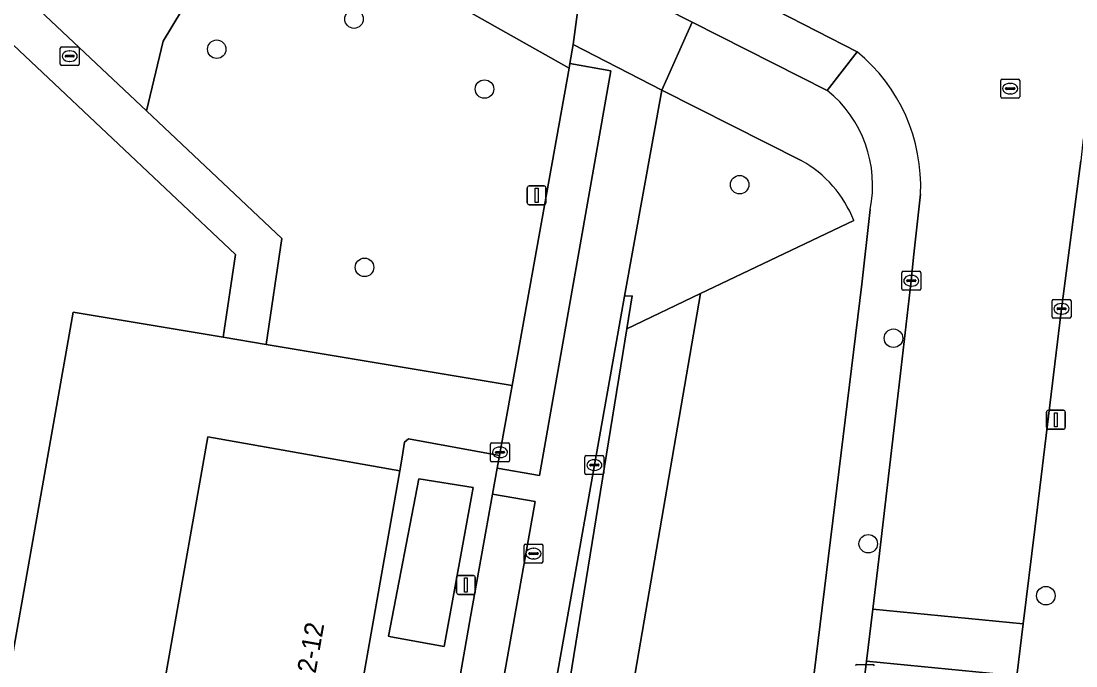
# Model space of a CAD drawing. Extents: x 161402 to 161933, y 381647 to 382315.
# Drawn here: x 161750.9 to 161806.7, y 381914.9 to 381949 of the extents above; entities that cross this region are included whole.
import ezdxf

# ---------------------------------------------------------------- set-up
doc = ezdxf.new("R2010")
doc.units = 0
for name, color, linetype in [('IMGEO_Boom', 7, 'Continuous'), ('IMGEO_Groenvoorziening', 7, 'Continuous'), ('IMGEO_Haag', 7, 'Continuous'), ('IMGEO_Kolk', 7, 'Continuous'), ('IMGEO_Lichtmast', 7, 'Continuous'), ('IMGEO_Pand', 7, 'Continuous'), ('IMGEO_Pand_nummerreeks', 7, 'Continuous'), ('IMGEO_Parkeervlak_open', 7, 'Continuous'), ('IMGEO_Rijbaan_lokaal_open', 7, 'Continuous'), ('IMGEO_Rioolput', 7, 'Continuous'), ('IMGEO_Voetpad_open', 7, 'Continuous')]:
    doc.layers.add(name, color=color, linetype=linetype)

msp = doc.modelspace()

# ---------------------------------------------------------------- linework, layer by layer
at = {"layer": 'IMGEO_Boom'}
for centre in [(161768.484, 381949.129), (161761.223, 381947.536), (161775.384, 381945.427), (161788.881, 381940.368), (161769.038, 381935.994), (161797.017, 381932.244), (161795.68, 381921.369), (161805.076, 381918.621)]:
    msp.add_circle(centre, 0.489, dxfattribs=at)
at = {"layer": 'IMGEO_Groenvoorziening'}
for points in [[(161757.71, 381973.064), (161752.256, 381970.922), (161752.331, 381970.789), (161752.352, 381970.751), (161756.323, 381963.676), (161759.452, 381960.205), (161755.303, 381956.704), (161754.882, 381956.037), (161751.868, 381949.589), (161757.507, 381944.274), (161758.386, 381947.963), (161763.392, 381956.267), (161767.079, 381953.278), (161771.629, 381951.189), (161779.856, 381946.528), (161779.9, 381946.775), (161780.082, 381947.784), (161780.63, 381951.898), (161779.002, 381952.721), (161777.972, 381953.284)], [(161737.696, 381886.61), (161738.528, 381891.149), (161746.013, 381890.587), (161753.635, 381933.615), (161761.561, 381932.294), (161762.216, 381936.676), (161748.594, 381949.514), (161744.47, 381949.999)], [(161793.514, 381945.349), (161786.367, 381948.968), (161784.762, 381945.37), (161792.141, 381941.646)], [(161792.141, 381941.646), (161784.762, 381945.37), (161782.784, 381934.462), (161783.2, 381934.478), (161782.918, 381932.741), (161786.816, 381934.618), (161794.921, 381938.465)], [(161795.348, 381935.098), (161795.777, 381939.049)], [(161794.921, 381938.465), (161786.816, 381934.618), (161779.814, 381893.915), (161788.716, 381884.216), (161790.718, 381897.39), (161795.348, 381935.098)], [(161768.961, 381885.978), (161758.322, 381887.744), (161758.545, 381889.099), (161758.611, 381889.504), (161754.257, 381890.274), (161757.508, 381908.649), (161760.759, 381927.025), (161770.911, 381925.228), (161771.029, 381925.951), (161771.159, 381926.744), (161771.362, 381926.92), (161776.174, 381926.042), (161776.84, 381929.749), (161763.83, 381931.916), (161761.561, 381932.294), (161753.635, 381933.615), (161746.013, 381890.587), (161744.878, 381884.178)]]:
    msp.add_lwpolyline(points, dxfattribs=at)
for points in [[(161757.507, 381944.274), (161764.668, 381937.525), (161763.83, 381931.916), (161776.84, 381929.749), (161779.856, 381946.528), (161771.629, 381951.189), (161767.079, 381953.278), (161763.392, 381956.267), (161758.386, 381947.963)], [(161764.668, 381937.525), (161757.507, 381944.274), (161751.868, 381949.589), (161749.618, 381951.709), (161744.458, 381952.316), (161744.47, 381949.999), (161748.594, 381949.514), (161762.216, 381936.676), (161761.561, 381932.294), (161763.83, 381931.916)], [(161782.918, 381932.741), (161783.2, 381934.478), (161782.784, 381934.462), (161775.497, 381893.39), (161776.5, 381893.226), (161776.924, 381895.837), (161777.092, 381896.872)], [(161779.814, 381893.915), (161786.816, 381934.618), (161782.918, 381932.741), (161777.092, 381896.872)], [(161774.788, 381924.343), (161771.914, 381924.8), (161770.307, 381916.473), (161770.437, 381916.449), (161773.256, 381915.934)]]:
    msp.add_lwpolyline(points, close=True, dxfattribs=at)
for centre, radius, start, end in [((161789.511, 381940.355), 6.401, 348.231, 51.2862), ((161789.052, 381936.141), 6.312, 21.6009, 60.702), ((161789.052, 381936.141), 6.312, 21.6009, 60.702)]:
    msp.add_arc(centre, radius, start, end, dxfattribs=at)
at = {"layer": 'IMGEO_Haag'}
msp.add_lwpolyline([(161782.918, 381932.741), (161783.2, 381934.478), (161782.784, 381934.462), (161775.497, 381893.39), (161776.5, 381893.226), (161776.924, 381895.837), (161777.092, 381896.872)], close=True, dxfattribs=at)
at = {"layer": 'IMGEO_Kolk'}
for p, q in [((161797.459, 381934.859), (161797.459, 381935.711)), ((161797.534, 381935.785), (161798.386, 381935.785)), ((161797.947, 381935.565), (161797.972, 381935.565)), ((161798.46, 381935.711), (161798.46, 381934.859)), ((161797.718, 381935.279), (161797.718, 381935.291)), ((161798.156, 381935.242), (161797.758, 381935.242)), ((161797.761, 381935.328), (161798.159, 381935.328)), ((161797.97, 381935.005), (161797.945, 381935.005)), ((161798.202, 381935.291), (161798.202, 381935.279)), ((161798.386, 381934.785), (161797.534, 381934.785)), ((161805.482, 381934.3), (161806.334, 381934.3)), ((161805.407, 381933.374), (161805.407, 381934.226)), ((161805.666, 381933.794), (161805.666, 381933.806)), ((161806.104, 381933.757), (161805.706, 381933.757)), ((161805.709, 381933.843), (161806.107, 381933.843)), ((161805.895, 381934.08), (161805.92, 381934.08)), ((161806.15, 381933.806), (161806.15, 381933.794)), ((161806.408, 381934.226), (161806.408, 381933.374)), ((161806.334, 381933.3), (161805.482, 381933.3)), ((161805.918, 381933.52), (161805.893, 381933.52)), ((161775.704, 381925.78), (161775.704, 381926.632)), ((161775.779, 381926.706), (161776.631, 381926.706)), ((161776.192, 381926.486), (161776.217, 381926.486)), ((161776.705, 381926.632), (161776.705, 381925.78)), ((161775.963, 381926.2), (161775.963, 381926.212)), ((161776.401, 381926.163), (161776.003, 381926.163)), ((161776.006, 381926.249), (161776.404, 381926.249)), ((161776.215, 381925.926), (161776.19, 381925.926)), ((161776.447, 381926.212), (161776.447, 381926.2)), ((161780.695, 381925.106), (161780.695, 381925.958)), ((161780.77, 381926.032), (161781.622, 381926.032)), ((161781.696, 381925.958), (161781.696, 381925.106)), ((161776.631, 381925.706), (161775.779, 381925.706)), ((161780.954, 381925.526), (161780.954, 381925.538)), ((161781.392, 381925.489), (161780.994, 381925.489)), ((161780.997, 381925.575), (161781.395, 381925.575)), ((161781.183, 381925.812), (161781.208, 381925.812)), ((161781.438, 381925.538), (161781.438, 381925.526)), ((161781.622, 381925.032), (161780.77, 381925.032)), ((161781.206, 381925.252), (161781.181, 381925.252)), ((161795.079, 381914.979), (161795.931, 381914.979))]:
    msp.add_line(p, q, dxfattribs=at)
for points in [[(161797.459, 381934.859), (161797.459, 381935.711)], [(161797.534, 381935.785), (161798.386, 381935.785)], [(161798.46, 381935.711), (161798.46, 381934.859)], [(161798.386, 381934.785), (161797.534, 381934.785)], [(161805.482, 381934.3), (161806.334, 381934.3)], [(161805.407, 381933.374), (161805.407, 381934.226)], [(161806.408, 381934.226), (161806.408, 381933.374)], [(161806.334, 381933.3), (161805.482, 381933.3)], [(161775.704, 381925.78), (161775.704, 381926.632)], [(161775.779, 381926.706), (161776.631, 381926.706)], [(161776.705, 381926.632), (161776.705, 381925.78)], [(161780.695, 381925.106), (161780.695, 381925.958)], [(161780.77, 381926.032), (161781.622, 381926.032)], [(161781.696, 381925.958), (161781.696, 381925.106)], [(161776.631, 381925.706), (161775.779, 381925.706)], [(161781.622, 381925.032), (161780.77, 381925.032)], [(161795.079, 381914.979), (161795.931, 381914.979)]]:
    msp.add_lwpolyline(points, dxfattribs=at)
for centre, radius, start, end in [((161797.536, 381935.709), 0.0765, 91.552, 178.448), ((161797.536, 381935.709), 0.0765, 91.552, 178.448), ((161798.384, 381935.709), 0.0765, 1.552, 88.448), ((161798.384, 381935.709), 0.0765, 1.552, 88.448), ((161797.536, 381934.861), 0.0765, 181.552, 268.448), ((161797.536, 381934.861), 0.0765, 181.552, 268.448), ((161797.758, 381935.288), 0.0403, 85.8775, 175.7526), ((161797.755, 381935.278), 0.0366, 178.938, 274.7102), ((161798.159, 381935.285), 0.043, 264.8664, 352.4533), ((161798.163, 381935.29), 0.0386, 1.7309, 96.639), ((161798.384, 381934.861), 0.0765, 271.552, 358.448), ((161798.384, 381934.861), 0.0765, 271.552, 358.448), ((161805.484, 381934.224), 0.0765, 91.552, 178.448), ((161805.484, 381934.224), 0.0765, 91.552, 178.448), ((161806.332, 381934.224), 0.0765, 1.552, 88.448), ((161806.332, 381934.224), 0.0765, 1.552, 88.448), ((161805.706, 381933.803), 0.0403, 85.8775, 175.7526), ((161805.703, 381933.793), 0.0366, 178.938, 274.7102), ((161806.107, 381933.8), 0.043, 264.8664, 352.4533), ((161806.111, 381933.805), 0.0386, 1.7309, 96.639), ((161805.484, 381933.376), 0.0765, 181.552, 268.448), ((161805.484, 381933.376), 0.0765, 181.552, 268.448), ((161806.332, 381933.376), 0.0765, 271.552, 358.448), ((161806.332, 381933.376), 0.0765, 271.552, 358.448), ((161775.781, 381926.63), 0.0765, 91.552, 178.448), ((161775.781, 381926.63), 0.0765, 91.552, 178.448), ((161776.629, 381926.63), 0.0765, 1.552, 88.448), ((161776.629, 381926.63), 0.0765, 1.552, 88.448), ((161776.003, 381926.209), 0.0403, 85.8775, 175.7526), ((161776, 381926.199), 0.0366, 178.938, 274.7102), ((161776.404, 381926.206), 0.043, 264.8664, 352.4533), ((161776.408, 381926.211), 0.0386, 1.7309, 96.639), ((161780.772, 381925.956), 0.0765, 91.552, 178.448), ((161780.772, 381925.956), 0.0765, 91.552, 178.448), ((161781.62, 381925.956), 0.0765, 1.552, 88.448), ((161781.62, 381925.956), 0.0765, 1.552, 88.448), ((161775.781, 381925.782), 0.0765, 181.552, 268.448), ((161775.781, 381925.782), 0.0765, 181.552, 268.448), ((161776.629, 381925.782), 0.0765, 271.552, 358.448), ((161776.629, 381925.782), 0.0765, 271.552, 358.448), ((161780.994, 381925.535), 0.0403, 85.8775, 175.7526), ((161780.991, 381925.525), 0.0366, 178.938, 274.7102), ((161781.395, 381925.532), 0.043, 264.8664, 352.4533), ((161781.399, 381925.537), 0.0386, 1.7309, 96.639), ((161780.772, 381925.108), 0.0765, 181.552, 268.448), ((161780.772, 381925.108), 0.0765, 181.552, 268.448), ((161781.62, 381925.108), 0.0765, 271.552, 358.448), ((161781.62, 381925.108), 0.0765, 271.552, 358.448), ((161795.081, 381914.903), 0.0765, 91.552, 178.448), ((161795.081, 381914.903), 0.0765, 91.552, 178.448), ((161795.929, 381914.903), 0.0765, 1.552, 88.448), ((161795.929, 381914.903), 0.0765, 1.552, 88.448)]:
    msp.add_arc(centre, radius, start, end, dxfattribs=at)
for centre, major_axis, ratio, start_param, end_param in [((161797.946, 381935.285), (-0.387, 0.002), 0.722429, 4.712389, 7.853982), ((161797.971, 381935.285), (-0.39, 0.002), 0.717154, 1.570796, 4.712389), ((161805.894, 381933.8), (-0.387, 0.002), 0.722429, 4.712389, 7.853982), ((161805.919, 381933.8), (-0.39, 0.002), 0.717154, 1.570796, 4.712389), ((161776.191, 381926.206), (-0.387, 0.002), 0.722429, 4.712389, 7.853982), ((161776.216, 381926.206), (-0.39, 0.002), 0.717154, 1.570796, 4.712389), ((161781.182, 381925.532), (-0.387, 0.002), 0.722429, 4.712389, 7.853982), ((161781.207, 381925.532), (-0.39, 0.002), 0.717154, 1.570796, 4.712389)]:
    msp.add_ellipse(centre, major_axis=major_axis, ratio=ratio, start_param=start_param, end_param=end_param, dxfattribs=at)
at = {"layer": 'IMGEO_Lichtmast'}
for p, q in [((161777.645, 381939.403), (161777.645, 381940.203)), ((161777.645, 381940.203), (161777.645, 381939.403)), ((161777.745, 381940.303), (161778.535, 381940.303)), ((161778.535, 381940.303), (161777.745, 381940.303)), ((161778.635, 381940.203), (161778.635, 381939.403)), ((161778.635, 381939.403), (161778.635, 381940.203)), ((161778.535, 381939.303), (161777.745, 381939.303)), ((161777.745, 381939.303), (161778.535, 381939.303)), ((161805.111, 381927.529), (161805.111, 381928.329)), ((161805.111, 381928.329), (161805.111, 381927.529)), ((161805.211, 381928.429), (161806.001, 381928.429)), ((161806.001, 381928.429), (161805.211, 381928.429)), ((161806.101, 381928.329), (161806.101, 381927.529)), ((161806.101, 381927.529), (161806.101, 381928.329)), ((161806.001, 381927.429), (161805.211, 381927.429)), ((161805.211, 381927.429), (161806.001, 381927.429)), ((161773.905, 381918.786), (161773.905, 381919.586)), ((161773.905, 381919.586), (161773.905, 381918.786)), ((161774.005, 381919.686), (161774.795, 381919.686)), ((161774.795, 381919.686), (161774.005, 381919.686)), ((161774.895, 381919.586), (161774.895, 381918.786)), ((161774.895, 381918.786), (161774.895, 381919.586)), ((161774.795, 381918.686), (161774.005, 381918.686)), ((161774.005, 381918.686), (161774.795, 381918.686))]:
    msp.add_line(p, q, dxfattribs=at)
for points in [[(161778.065, 381940.178), (161778.215, 381940.178), (161778.215, 381939.428), (161778.065, 381939.428), (161778.065, 381940.178)], [(161805.531, 381928.304), (161805.681, 381928.304), (161805.681, 381927.554), (161805.531, 381927.554), (161805.531, 381928.304)], [(161774.325, 381919.561), (161774.475, 381919.561), (161774.475, 381918.811), (161774.325, 381918.811), (161774.325, 381919.561)]]:
    msp.add_lwpolyline(points, dxfattribs=at)
for centre, start, end in [((161777.745, 381940.203), 90, 180), ((161777.745, 381940.203), 90, 180), ((161778.535, 381940.203), 0, 90), ((161778.535, 381940.203), 360, 90), ((161777.745, 381939.403), 180, 270), ((161777.745, 381939.403), 180, 270), ((161778.535, 381939.403), 270, 0), ((161778.535, 381939.403), 270, 0), ((161805.211, 381928.329), 90, 180), ((161805.211, 381928.329), 90, 180), ((161806.001, 381928.329), 0, 90), ((161806.001, 381928.329), 360, 90), ((161805.211, 381927.529), 180, 270), ((161805.211, 381927.529), 180, 270), ((161806.001, 381927.529), 270, 0), ((161806.001, 381927.529), 270, 0), ((161774.005, 381919.586), 90, 180), ((161774.005, 381919.586), 90, 180), ((161774.795, 381919.586), 0, 90), ((161774.795, 381919.586), 360, 90), ((161774.005, 381918.786), 180, 270), ((161774.005, 381918.786), 180, 270), ((161774.795, 381918.786), 270, 0), ((161774.795, 381918.786), 270, 0)]:
    msp.add_arc(centre, 0.1, start, end, dxfattribs=at)
at = {"layer": 'IMGEO_Pand'}
msp.add_lwpolyline([(161757.508, 381908.649), (161767.659, 381906.853), (161770.911, 381925.228), (161760.759, 381927.025)], close=True, dxfattribs=at)
at = {"layer": 'IMGEO_Parkeervlak_open'}
for points in [[(161779.9, 381946.775), (161779.856, 381946.528), (161776.84, 381929.749), (161776.174, 381926.042), (161776.054, 381925.369), (161778.29, 381924.974), (161782.071, 381946.391)], [(161786.796, 381870.79), (161771.319, 381885.533), (161771.355, 381885.738), (161776.189, 381913.114), (161778.071, 381923.6), (161775.809, 381923.999), (161774.646, 381917.502), (161772.935, 381907.756), (161770.541, 381894.588), (161768.961, 381885.978), (161769.381, 381884.923), (161769.662, 381884.07), (161771.638, 381881.858), (161773.952, 381879.809), (161774.308, 381879.519), (161775.214, 381878.728), (161778.453, 381875.613), (161785.266, 381869.061), (161786.294, 381868.013)]]:
    msp.add_lwpolyline(points, close=True, dxfattribs=at)
at = {"layer": 'IMGEO_Rijbaan_lokaal_open'}
for points in [[(161798.03, 381950.977), (161796.605, 381951.684), (161791.589, 381954.222), (161784.276, 381957.939), (161782, 381954.061), (161790.834, 381949.58), (161795.097, 381947.398)], [(161782.784, 381934.462), (161784.762, 381945.37), (161780.082, 381947.784), (161779.9, 381946.775), (161782.071, 381946.391), (161778.29, 381924.974), (161776.054, 381925.369), (161775.809, 381923.999), (161778.071, 381923.6), (161776.189, 381913.114), (161771.355, 381885.738), (161771.319, 381885.533), (161786.796, 381870.79), (161787.303, 381874.33), (161777.78, 381883.315)], [(161798.445, 381939.863), (161798.081, 381936.527), (161797.961, 381935.28), (161797.368, 381930.233), (161796.239, 381920.546), (161795.921, 381917.91), (161803.877, 381917.126), (161804.496, 381922.134), (161805.889, 381933.665), (161806.923, 381941.638)], [(161774.971, 381890.426), (161775.497, 381893.39), (161782.784, 381934.462)], [(161800.123, 381888.098), (161801.051, 381895.224), (161801.89, 381901.53), (161803.118, 381910.861), (161803.538, 381914.387), (161795.589, 381915.163), (161794.834, 381908.914), (161793.848, 381901.629), (161792.734, 381893.144), (161791.514, 381883.928), (161790.235, 381874.932), (161790.05, 381873.849), (161788.629, 381865.767), (161788.553, 381865.406), (161789.857, 381865.169)]]:
    msp.add_lwpolyline(points, dxfattribs=at)
for points in [[(161786.367, 381948.968), (161780.63, 381951.898), (161780.082, 381947.784), (161784.762, 381945.37)], [(161803.877, 381917.126), (161795.921, 381917.91), (161795.589, 381915.163), (161803.538, 381914.387)]]:
    msp.add_lwpolyline(points, close=True, dxfattribs=at)
msp.add_arc((161789.265, 381940.295), 9.191, 357.3045, 50.6092, dxfattribs=at)
at = {"layer": 'IMGEO_Rioolput'}
for p, q in [((161753.02, 381947.669), (161753.872, 381947.669)), ((161752.945, 381946.743), (161752.945, 381947.595)), ((161753.204, 381947.163), (161753.204, 381947.175)), ((161753.642, 381947.126), (161753.244, 381947.126)), ((161753.247, 381947.212), (161753.645, 381947.212)), ((161753.433, 381947.449), (161753.458, 381947.449)), ((161753.688, 381947.175), (161753.688, 381947.163)), ((161753.946, 381947.595), (161753.946, 381946.743)), ((161753.872, 381946.669), (161753.02, 381946.669)), ((161753.456, 381946.889), (161753.431, 381946.889)), ((161802.691, 381945.024), (161802.691, 381945.876)), ((161802.766, 381945.95), (161803.618, 381945.95)), ((161802.95, 381945.444), (161802.95, 381945.456)), ((161802.993, 381945.493), (161803.391, 381945.493)), ((161803.179, 381945.73), (161803.204, 381945.73)), ((161803.434, 381945.456), (161803.434, 381945.444)), ((161803.692, 381945.876), (161803.692, 381945.024)), ((161803.618, 381944.95), (161802.766, 381944.95)), ((161803.388, 381945.407), (161802.99, 381945.407)), ((161803.202, 381945.17), (161803.177, 381945.17)), ((161777.478, 381920.421), (161777.478, 381921.273)), ((161777.553, 381921.347), (161778.405, 381921.347)), ((161777.78, 381920.89), (161778.178, 381920.89)), ((161777.966, 381921.127), (161777.991, 381921.127)), ((161778.479, 381921.273), (161778.479, 381920.421)), ((161778.405, 381920.347), (161777.553, 381920.347)), ((161777.737, 381920.841), (161777.737, 381920.853)), ((161778.175, 381920.804), (161777.777, 381920.804)), ((161777.989, 381920.567), (161777.964, 381920.567)), ((161778.221, 381920.853), (161778.221, 381920.841))]:
    msp.add_line(p, q, dxfattribs=at)
for points in [[(161753.02, 381947.669), (161753.872, 381947.669)], [(161752.945, 381946.743), (161752.945, 381947.595)], [(161753.946, 381947.595), (161753.946, 381946.743)], [(161753.872, 381946.669), (161753.02, 381946.669)], [(161802.691, 381945.024), (161802.691, 381945.876)], [(161802.766, 381945.95), (161803.618, 381945.95)], [(161803.692, 381945.876), (161803.692, 381945.024)], [(161803.618, 381944.95), (161802.766, 381944.95)], [(161777.478, 381920.421), (161777.478, 381921.273)], [(161777.553, 381921.347), (161778.405, 381921.347)], [(161778.479, 381921.273), (161778.479, 381920.421)], [(161778.405, 381920.347), (161777.553, 381920.347)]]:
    msp.add_lwpolyline(points, dxfattribs=at)
for centre, radius, start, end in [((161753.022, 381947.593), 0.0765, 91.552, 178.448), ((161753.022, 381947.593), 0.0765, 91.552, 178.448), ((161753.87, 381947.593), 0.0765, 1.552, 88.448), ((161753.87, 381947.593), 0.0765, 1.552, 88.448), ((161753.244, 381947.172), 0.0403, 85.8775, 175.7526), ((161753.241, 381947.162), 0.0366, 178.938, 274.7102), ((161753.645, 381947.169), 0.043, 264.8664, 352.4533), ((161753.649, 381947.174), 0.0386, 1.7309, 96.639), ((161753.022, 381946.745), 0.0765, 181.552, 268.448), ((161753.022, 381946.745), 0.0765, 181.552, 268.448), ((161753.87, 381946.745), 0.0765, 271.552, 358.448), ((161753.87, 381946.745), 0.0765, 271.552, 358.448), ((161802.768, 381945.874), 0.0765, 91.552, 178.448), ((161802.768, 381945.874), 0.0765, 91.552, 178.448), ((161802.99, 381945.453), 0.0403, 85.8775, 175.7526), ((161802.987, 381945.443), 0.0366, 178.938, 274.7102), ((161803.391, 381945.45), 0.043, 264.8664, 352.4533), ((161803.395, 381945.455), 0.0386, 1.7309, 96.639), ((161803.616, 381945.874), 0.0765, 1.552, 88.448), ((161803.616, 381945.874), 0.0765, 1.552, 88.448), ((161802.768, 381945.026), 0.0765, 181.552, 268.448), ((161802.768, 381945.026), 0.0765, 181.552, 268.448), ((161803.616, 381945.026), 0.0765, 271.552, 358.448), ((161803.616, 381945.026), 0.0765, 271.552, 358.448), ((161777.555, 381921.271), 0.0765, 91.552, 178.448), ((161777.555, 381921.271), 0.0765, 91.552, 178.448), ((161777.777, 381920.85), 0.0403, 85.8775, 175.7526), ((161778.182, 381920.852), 0.0386, 1.7309, 96.639), ((161778.403, 381921.271), 0.0765, 1.552, 88.448), ((161778.403, 381921.271), 0.0765, 1.552, 88.448), ((161777.555, 381920.423), 0.0765, 181.552, 268.448), ((161777.555, 381920.423), 0.0765, 181.552, 268.448), ((161777.774, 381920.84), 0.0366, 178.938, 274.7102), ((161778.178, 381920.847), 0.043, 264.8664, 352.4533), ((161778.403, 381920.423), 0.0765, 271.552, 358.448), ((161778.403, 381920.423), 0.0765, 271.552, 358.448)]:
    msp.add_arc(centre, radius, start, end, dxfattribs=at)
for centre, major_axis, ratio, start_param, end_param in [((161753.432, 381947.169), (-0.387, 0.002), 0.722429, 4.712389, 7.853982), ((161753.457, 381947.169), (-0.39, 0.002), 0.717154, 1.570796, 4.712389), ((161803.178, 381945.45), (-0.387, 0.002), 0.722429, 4.712389, 7.853982), ((161803.203, 381945.45), (-0.39, 0.002), 0.717154, 1.570796, 4.712389), ((161777.965, 381920.847), (-0.387, 0.002), 0.722429, 4.712389, 7.853982), ((161777.99, 381920.847), (-0.39, 0.002), 0.717154, 1.570796, 4.712389)]:
    msp.add_ellipse(centre, major_axis=major_axis, ratio=ratio, start_param=start_param, end_param=end_param, dxfattribs=at)
at = {"layer": 'IMGEO_Voetpad_open'}
for points in [[(161777.972, 381953.284), (161779.002, 381952.721), (161780.63, 381951.898), (161786.367, 381948.968), (161793.514, 381945.349), (161795.097, 381947.398), (161790.834, 381949.58), (161782, 381954.061)], [(161795.097, 381947.398), (161793.514, 381945.349)], [(161807.058, 381942.789), (161806.923, 381941.638), (161805.889, 381933.665), (161804.496, 381922.134), (161803.877, 381917.126), (161803.538, 381914.387), (161803.118, 381910.861), (161801.89, 381901.53), (161801.051, 381895.224), (161800.123, 381888.098), (161798.914, 381879.502), (161797.756, 381871.795), (161795.424, 381857.71), (161795.166, 381856.272), (161794.937, 381855.018), (161793.286, 381846.409), (161793.776, 381846.311), (161791.404, 381834.353), (161790.913, 381834.452), (161789.643, 381828.457)], [(161795.589, 381915.163), (161795.921, 381917.91), (161796.239, 381920.546), (161797.368, 381930.233), (161797.961, 381935.28), (161798.081, 381936.527), (161798.445, 381939.863)], [(161795.777, 381939.049), (161795.348, 381935.098), (161790.718, 381897.39), (161788.716, 381884.216), (161787.345, 381874.628), (161787.303, 381874.33), (161790.05, 381873.849), (161790.235, 381874.932), (161791.514, 381883.928), (161792.734, 381893.144), (161793.848, 381901.629), (161794.834, 381908.914), (161795.589, 381915.163)]]:
    msp.add_lwpolyline(points, dxfattribs=at)
for points in [[(161772.935, 381907.756), (161774.646, 381917.502), (161775.809, 381923.999), (161776.054, 381925.369), (161776.174, 381926.042), (161771.362, 381926.92), (161771.159, 381926.744), (161771.029, 381925.951), (161770.911, 381925.228), (161767.659, 381906.853), (161764.408, 381888.478), (161758.611, 381889.504), (161758.545, 381889.099), (161758.322, 381887.744), (161768.961, 381885.978), (161770.541, 381894.588)], [(161770.307, 381916.473), (161771.914, 381924.8), (161774.788, 381924.343), (161773.256, 381915.934), (161770.437, 381916.449)]]:
    msp.add_lwpolyline(points, close=True, dxfattribs=at)
for centre, radius, start, end in [((161789.265, 381940.295), 9.191, 357.3045, 50.6092), ((161789.511, 381940.355), 6.401, 348.231, 51.2862)]:
    msp.add_arc(centre, radius, start, end, dxfattribs=at)

# ---------------------------------------------------------------- texts
at = {"layer": 'IMGEO_Pand_nummerreeks'}
msp.add_text('2-12', height=1, rotation=79.9653, dxfattribs=at).set_placement((161766.449, 381914.474))

doc.saveas('drawing.dxf')
